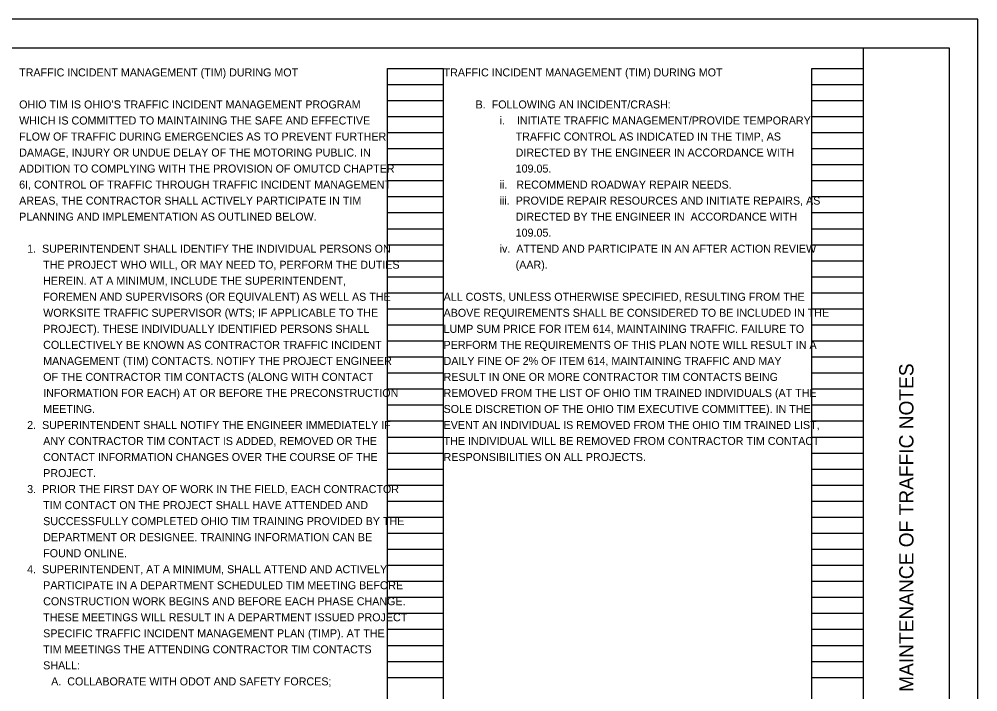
# Model space of a CAD drawing. Extents: x 0 to 69.3, y 0 to 22.
# Drawn here: x 17.24 to 34, y 10.25 to 22 of the extents above; entities that cross this region are included whole.
import ezdxf

# ---------------------------------------------------------------- set-up
doc = ezdxf.new("R2010")
doc.units = 0
for name, color, linetype in [('SH_Border', 7, 'Continuous'), ('SH_Cut_Line', 7, 'Continuous'), ('SH_Data', 7, 'Continuous'), ('SH_Text', 7, 'Continuous')]:
    doc.layers.add(name, color=color, linetype=linetype)

msp = doc.modelspace()

# ---------------------------------------------------------------- linework, layer by layer
at = {"layer": 'SH_Border'}
msp.add_line((32, 0.5), (32, 21.5), dxfattribs=at)
msp.add_lwpolyline([(1.5, 21.5), (33.5, 21.5), (33.5, 0.5), (1.5, 0.5)], close=True, dxfattribs=at)
at = {"layer": 'SH_Cut_Line'}
msp.add_lwpolyline([(0, 0), (34, 0), (34, 22), (0, 22)], close=True, dxfattribs=at)
at = {"layer": 'SH_Data'}
for p, q in [((23.68, 0.98), (23.68, 21.14)), ((23.68, 21.14), (24.66, 21.14)), ((24.66, 0.98), (24.66, 21.14)), ((31.1, 0.98), (31.1, 21.14)), ((31.1, 21.14), (32, 21.14)), ((32, 0.98), (32, 21.14)), ((23.68, 20.86), (24.66, 20.86)), ((31.1, 20.86), (32, 20.86)), ((23.68, 20.58), (24.66, 20.58)), ((31.1, 20.58), (32, 20.58)), ((23.68, 20.3), (24.66, 20.3)), ((31.1, 20.3), (32, 20.3)), ((23.68, 20.02), (24.66, 20.02)), ((31.1, 20.02), (32, 20.02)), ((23.68, 19.74), (24.66, 19.74)), ((31.1, 19.74), (32, 19.74)), ((23.68, 19.46), (24.66, 19.46)), ((31.1, 19.46), (32, 19.46)), ((23.68, 19.18), (24.66, 19.18)), ((31.1, 19.18), (32, 19.18)), ((23.68, 18.9), (24.66, 18.9)), ((31.1, 18.9), (32, 18.9)), ((23.68, 18.62), (24.66, 18.62)), ((31.1, 18.62), (32, 18.62)), ((23.68, 18.34), (24.66, 18.34)), ((31.1, 18.34), (32, 18.34)), ((23.68, 18.06), (24.66, 18.06)), ((31.1, 18.06), (32, 18.06)), ((23.68, 17.78), (24.66, 17.78)), ((31.1, 17.78), (32, 17.78)), ((23.68, 17.5), (24.66, 17.5)), ((31.1, 17.5), (32, 17.5)), ((23.68, 17.22), (24.66, 17.22)), ((31.1, 17.22), (32, 17.22)), ((23.68, 16.94), (24.66, 16.94)), ((31.1, 16.94), (32, 16.94)), ((23.68, 16.66), (24.66, 16.66)), ((31.1, 16.66), (32, 16.66)), ((23.68, 16.38), (24.66, 16.38)), ((31.1, 16.38), (32, 16.38)), ((23.68, 16.1), (24.66, 16.1)), ((31.1, 16.1), (32, 16.1)), ((23.68, 15.82), (24.66, 15.82)), ((31.1, 15.82), (32, 15.82)), ((23.68, 15.54), (24.66, 15.54)), ((31.1, 15.54), (32, 15.54)), ((23.68, 15.26), (24.66, 15.26)), ((31.1, 15.26), (32, 15.26)), ((23.68, 14.98), (24.66, 14.98)), ((31.1, 14.98), (32, 14.98)), ((23.68, 14.7), (24.66, 14.7)), ((31.1, 14.7), (32, 14.7)), ((23.68, 14.42), (24.66, 14.42)), ((31.1, 14.42), (32, 14.42)), ((23.68, 14.14), (24.66, 14.14)), ((31.1, 14.14), (32, 14.14)), ((23.68, 13.86), (24.66, 13.86)), ((31.1, 13.86), (32, 13.86)), ((23.68, 13.58), (24.66, 13.58)), ((31.1, 13.58), (32, 13.58)), ((23.68, 13.3), (24.66, 13.3)), ((31.1, 13.3), (32, 13.3)), ((23.68, 13.02), (24.66, 13.02)), ((31.1, 13.02), (32, 13.02)), ((23.68, 12.74), (24.66, 12.74)), ((31.1, 12.74), (32, 12.74)), ((23.68, 12.46), (24.66, 12.46)), ((31.1, 12.46), (32, 12.46)), ((23.68, 12.18), (24.66, 12.18)), ((31.1, 12.18), (32, 12.18)), ((23.68, 11.9), (24.66, 11.9)), ((31.1, 11.9), (32, 11.9)), ((23.68, 11.62), (24.66, 11.62)), ((31.1, 11.62), (32, 11.62)), ((23.68, 11.34), (24.66, 11.34)), ((31.1, 11.34), (32, 11.34)), ((23.68, 11.06), (24.66, 11.06)), ((31.1, 11.06), (32, 11.06)), ((23.68, 10.78), (24.66, 10.78)), ((31.1, 10.78), (32, 10.78)), ((23.68, 10.5), (24.66, 10.5)), ((31.1, 10.5), (32, 10.5))]:
    msp.add_line(p, q, dxfattribs=at)

# ---------------------------------------------------------------- texts
msp.add_text('MAINTENANCE OF TRAFFIC NOTES', height=0.25, rotation=90, dxfattribs=at).set_placement((32.875, 10.247))
at = {"layer": 'SH_Text'}
for s, p in [('TRAFFIC INCIDENT MANAGEMENT (TIM) DURING MOT', (17.24, 21)), ('TRAFFIC INCIDENT MANAGEMENT (TIM) DURING MOT', (24.66, 21)), ('OHIO TIM IS OHIO’S TRAFFIC INCIDENT MANAGEMENT PROGRAM ', (17.24, 20.44)), ('B.  FOLLOWING AN INCIDENT/CRASH: ', (25.22, 20.44)), ('WHICH IS COMMITTED TO MAINTAINING THE SAFE AND EFFECTIVE ', (17.24, 20.16)), ('i.    INITIATE TRAFFIC MANAGEMENT/PROVIDE TEMPORARY ', (25.64, 20.16)), ('FLOW OF TRAFFIC DURING EMERGENCIES AS TO PREVENT FURTHER ', (17.24, 19.88)), ('TRAFFIC CONTROL AS INDICATED IN THE TIMP, AS ', (25.92, 19.88)), ('DAMAGE, INJURY OR UNDUE DELAY OF THE MOTORING PUBLIC. IN ', (17.24, 19.6)), ('DIRECTED BY THE ENGINEER IN ACCORDANCE WITH ', (25.92, 19.6)), ('ADDITION TO COMPLYING WITH THE PROVISION OF OMUTCD CHAPTER ', (17.24, 19.32)), ('109.05. ', (25.92, 19.32)), ('6I, CONTROL OF TRAFFIC THROUGH TRAFFIC INCIDENT MANAGEMENT ', (17.24, 19.04)), ('ii.   RECOMMEND ROADWAY REPAIR NEEDS.', (25.64, 19.04)), ('AREAS, THE CONTRACTOR SHALL ACTIVELY PARTICIPATE IN TIM ', (17.24, 18.76)), ('iii.  PROVIDE REPAIR RESOURCES AND INITIATE REPAIRS, AS ', (25.64, 18.76)), ('PLANNING AND IMPLEMENTATION AS OUTLINED BELOW.', (17.24, 18.48)), ('DIRECTED BY THE ENGINEER IN  ACCORDANCE WITH ', (25.92, 18.48)), ('109.05. ', (25.92, 18.2)), ('1.  SUPERINTENDENT SHALL IDENTIFY THE INDIVIDUAL PERSONS ON ', (17.38, 17.92)), ('iv.  ATTEND AND PARTICIPATE IN AN AFTER ACTION REVIEW ', (25.64, 17.92)), ('THE PROJECT WHO WILL, OR MAY NEED TO, PERFORM THE DUTIES ', (17.66, 17.64)), ('(AAR). ', (25.92, 17.64)), ('HEREIN. AT A MINIMUM, INCLUDE THE SUPERINTENDENT, ', (17.66, 17.36)), ('FOREMEN AND SUPERVISORS (OR EQUIVALENT) AS WELL AS THE ', (17.66, 17.08)), ('ALL COSTS, UNLESS OTHERWISE SPECIFIED, RESULTING FROM THE ', (24.66, 17.08)), ('WORKSITE TRAFFIC SUPERVISOR (WTS; IF APPLICABLE TO THE ', (17.66, 16.8)), ('ABOVE REQUIREMENTS SHALL BE CONSIDERED TO BE INCLUDED IN THE ', (24.66, 16.8)), ('PROJECT). THESE INDIVIDUALLY IDENTIFIED PERSONS SHALL ', (17.66, 16.52)), ('LUMP SUM PRICE FOR ITEM 614, MAINTAINING TRAFFIC. FAILURE TO ', (24.66, 16.52)), ('COLLECTIVELY BE KNOWN AS CONTRACTOR TRAFFIC INCIDENT ', (17.66, 16.24)), ('PERFORM THE REQUIREMENTS OF THIS PLAN NOTE WILL RESULT IN A ', (24.66, 16.24)), ('MANAGEMENT (TIM) CONTACTS. NOTIFY THE PROJECT ENGINEER ', (17.66, 15.96)), ('DAILY FINE OF 2% OF ITEM 614, MAINTAINING TRAFFIC AND MAY ', (24.66, 15.96)), ('OF THE CONTRACTOR TIM CONTACTS (ALONG WITH CONTACT ', (17.66, 15.68)), ('RESULT IN ONE OR MORE CONTRACTOR TIM CONTACTS BEING ', (24.66, 15.68)), ('INFORMATION FOR EACH) AT OR BEFORE THE PRECONSTRUCTION ', (17.66, 15.4)), ('REMOVED FROM THE LIST OF OHIO TIM TRAINED INDIVIDUALS (AT THE ', (24.66, 15.4)), ('MEETING. ', (17.66, 15.12)), ('SOLE DISCRETION OF THE OHIO TIM EXECUTIVE COMMITTEE). IN THE ', (24.66, 15.12)), ('2.  SUPERINTENDENT SHALL NOTIFY THE ENGINEER IMMEDIATELY IF ', (17.38, 14.84)), ('EVENT AN INDIVIDUAL IS REMOVED FROM THE OHIO TIM TRAINED LIST, ', (24.66, 14.84)), ('ANY CONTRACTOR TIM CONTACT IS ADDED, REMOVED OR THE ', (17.66, 14.56)), ('THE INDIVIDUAL WILL BE REMOVED FROM CONTRACTOR TIM CONTACT ', (24.66, 14.56)), ('CONTACT INFORMATION CHANGES OVER THE COURSE OF THE ', (17.66, 14.28)), ('RESPONSIBILITIES ON ALL PROJECTS.  ', (24.66, 14.28)), ('PROJECT. ', (17.66, 14)), ('3.  PRIOR THE FIRST DAY OF WORK IN THE FIELD, EACH CONTRACTOR ', (17.38, 13.72)), ('TIM CONTACT ON THE PROJECT SHALL HAVE ATTENDED AND ', (17.66, 13.44)), ('SUCCESSFULLY COMPLETED OHIO TIM TRAINING PROVIDED BY THE ', (17.66, 13.16)), ('DEPARTMENT OR DESIGNEE. TRAINING INFORMATION CAN BE ', (17.66, 12.88)), ('FOUND ONLINE. ', (17.66, 12.6)), ('4.  SUPERINTENDENT, AT A MINIMUM, SHALL ATTEND AND ACTIVELY ', (17.38, 12.32)), ('PARTICIPATE IN A DEPARTMENT SCHEDULED TIM MEETING BEFORE ', (17.66, 12.04)), ('CONSTRUCTION WORK BEGINS AND BEFORE EACH PHASE CHANGE. ', (17.66, 11.76)), ('THESE MEETINGS WILL RESULT IN A DEPARTMENT ISSUED PROJECT ', (17.66, 11.48)), ('SPECIFIC TRAFFIC INCIDENT MANAGEMENT PLAN (TIMP). AT THE ', (17.66, 11.2)), ('TIM MEETINGS THE ATTENDING CONTRACTOR TIM CONTACTS ', (17.66, 10.92)), ('SHALL:', (17.66, 10.64)), ('A.  COLLABORATE WITH ODOT AND SAFETY FORCES; ', (17.8, 10.36))]:
    msp.add_text(s, height=0.14, dxfattribs=at).set_placement(p)

doc.saveas('drawing.dxf')
